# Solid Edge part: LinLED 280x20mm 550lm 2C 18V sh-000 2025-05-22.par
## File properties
Author: jaroslaw.przewlocki
Template: iso metric part.par
Last saved by: jaroslaw.przewlocki
Revision: 1
Application: Solid Edge
Gęstość: 0,000 kg/m^3
Dokładność: 0,990
Username: jaroslaw.przewlocki
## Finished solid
Body 1: solid body, 829 faces, 2128 edges, 1357 vertices.
  Faces by surface: plane 511, cylinder 155, torus 68, cone 50, spline 24, sphere 21
  Edges by curve: line 1462, curve on surface 360, circle 201, ellipse 71, spline 34
Bounding box of the edges (mm; curved faces can reach further): 279.600 x 20.000 x 4.450, from (-139.8, -10, -1) to (139.8, 10, 3.45).
Cylindrical faces by radius (mm): R0.1 x6, R0.2 x46, R0.2169 x6, R0.25 x22, R0.3373 x6, R0.4 x8, R0.4006 x2, R0.4008 x2, R0.525 x2, R0.6 x20, R1 x12, R1.1 x4, R1.1989 x2, R1.199 x2, R1.2 x10, R2.15 x5
Conical faces (half-angle, radius in mm at the cone's reference point): 0.398 deg R1.1964 x2, 0.4493 deg R1.1964 x2, 0.4746 deg R1.1948 x2, 0.4758 deg R1.1948 x2, 0.5 deg R0.5056 x4, 0.5 deg R1.0082 x4, 1 deg R0.5511 x2, 10 deg R0.2132 x4, 10 deg R0.4132 x4, 16.0099 deg R1.1053 x2, 16.1249 deg R1.1279 x2, 18.8604 deg R1.0669 x4, 19.5041 deg R0.5138 x2, 19.8244 deg R0.5099 x2, 27.363 deg R0.6214 x2, 40.6434 deg R0.5161 x2, 43.3309 deg R0.4892 x2, 45 deg R0.575 x2, 45 deg R0.625 x4
Toroidal faces (ring radius, tube radius in mm): R0.0958 r0.3997 x4, R0.1076 r0.4 x2, R0.1101 r0.4001 x2, R0.1217 r0.4 x2, R0.1234 r0.4 x2, R0.1626 r0.228 x2, R0.1634 r0.2287 x2, R0.3287 r0.2001 x2, R0.3322 r0.2 x2, R0.3684 r0.2151 x2, R0.3703 r0.4 x2, R0.3818 r0.2 x4, R0.4166 r0.3983 x2, R0.5981 r0.197 x2, R0.5982 r0.197 x2, R0.6009 r0.3968 x2, R0.6009 r0.3969 x2, R0.6227 r0.2 x2, R0.6235 r0.2 x2, R0.8 r0.2 x4, R0.8522 r0.3 x2, R0.9002 r0.2 x2, R0.9018 r0.2 x2, R0.9197 r0.223 x2, R0.9365 r0.2 x2, R0.9663 r0.2263 x2, R0.9665 r0.2263 x2, R1.2 r0.1 x2, R1.429 r1.2 x2, R1.8741 r0.2175 x2, R1.9007 r0.2 x2
Spherical faces by radius (mm): R0.1 x5, R0.2 x12, R0.6 x4
Planar faces by outward normal: +x 57, +y 60, +z 81, -x 57, -y 61, -z 9, oblique 186
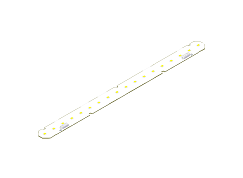
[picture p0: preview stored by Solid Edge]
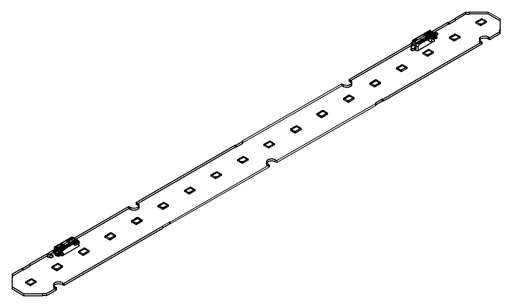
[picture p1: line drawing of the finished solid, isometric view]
